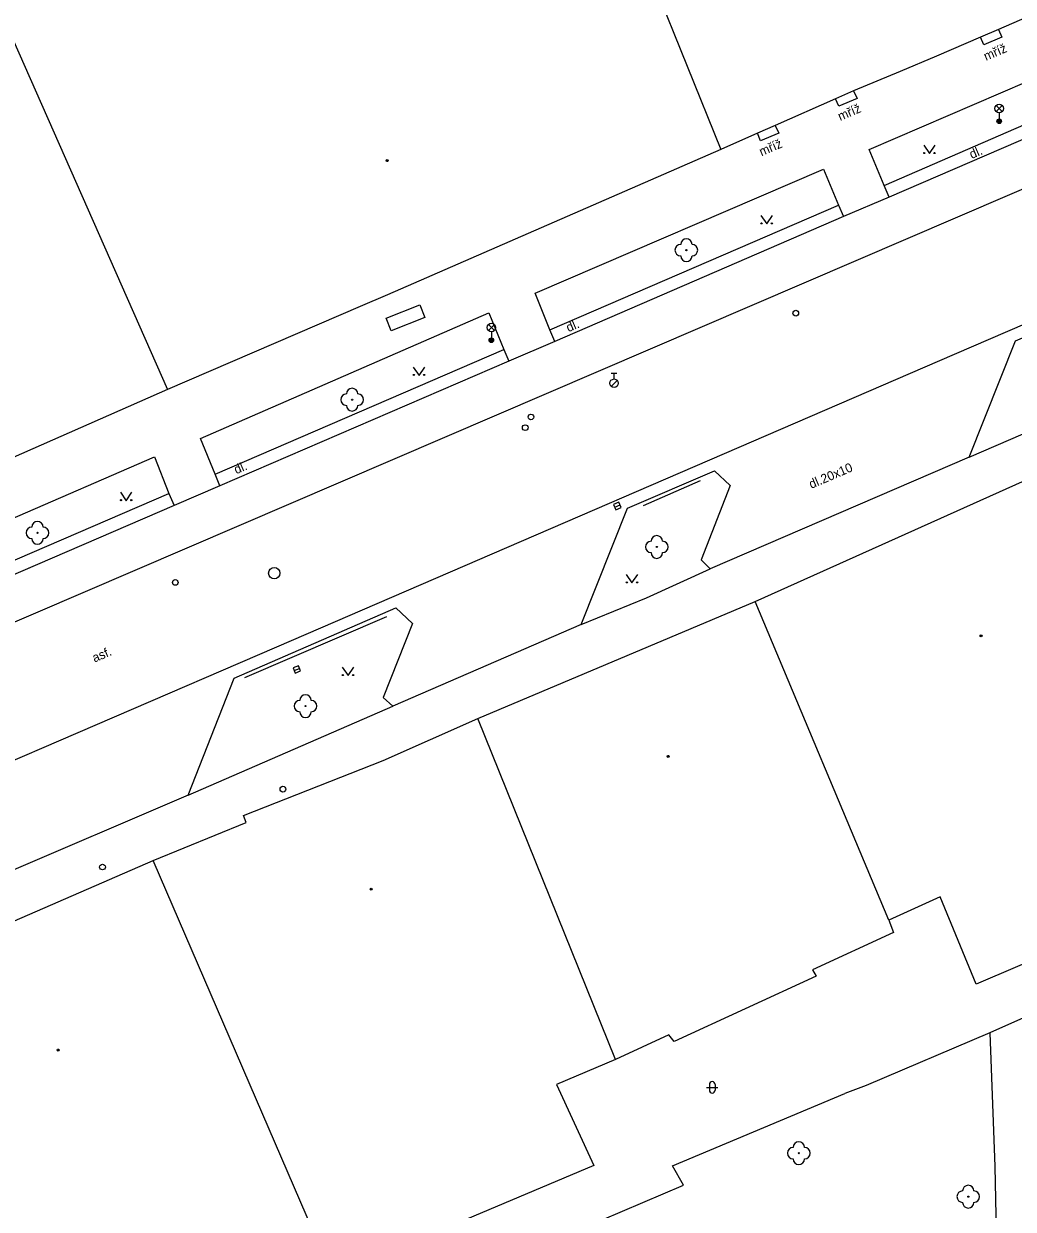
# Model space of a CAD drawing. Extents: x -599770 to -598493, y -1162076 to -1159209.
# Drawn here: x -599478.9 to -599435.5, y -1161229.9 to -1161177.8 of the extents above; entities that cross this region are included whole.
import ezdxf

# ---------------------------------------------------------------- set-up
doc = ezdxf.new("R2010")
doc.units = 0
doc.layers.add('Podklad', color=7, linetype='Continuous')

msp = doc.modelspace()

# ---------------------------------------------------------------- linework, layer by layer
at = {"layer": 'Podklad'}
for p, q in [((-599436.203, -1161181.68), (-599435.938, -1161181.415)), ((-599436.203, -1161181.415), (-599435.938, -1161181.68)), ((-599436.07, -1161181.735), (-599436.07, -1161182.11)), ((-599458.523, -1161191.3), (-599458.258, -1161191.035)), ((-599458.523, -1161191.035), (-599458.258, -1161191.3)), ((-599458.39, -1161191.355), (-599458.39, -1161191.73)), ((-599453.125, -1161193.183), (-599452.875, -1161193.183)), ((-599453, -1161193.433), (-599453, -1161193.183)), ((-599453.129, -1161193.756), (-599452.864, -1161193.491)), ((-599452.964, -1161199.06), (-599452.736, -1161198.96)), ((-599467.055, -1161206.238), (-599466.825, -1161206.142)), ((-599448.933, -1161224.548), (-599448.433, -1161224.548)), ((-599448.808, -1161224.423), (-599448.808, -1161224.673)), ((-599448.558, -1161224.423), (-599448.558, -1161224.673))]:
    msp.add_line(p, q, dxfattribs=at)
for points in [[(-599452.75, -1161172.35), (-599448.3, -1161183.35)], [(-599433.37, -1161176.9), (-599436.1, -1161178.08)], [(-599517.213, -1161220.408), (-599480.808, -1161204.724), (-599417.53, -1161177.569)], [(-599479.66, -1161177.97), (-599472.63, -1161193.89)], [(-599441.12, -1161184.93), (-599441.78, -1161183.35), (-599429.05, -1161177.88), (-599428.41, -1161179.41)], [(-599436.1, -1161178.08), (-599436.9, -1161178.42)], [(-599436.1, -1161178.08), (-599435.95, -1161178.42), (-599436.75, -1161178.76), (-599436.9, -1161178.42)], [(-599436.9, -1161178.42), (-599438.83, -1161179.25)], [(-599438.83, -1161179.25), (-599440.43, -1161179.93)], [(-599441.12, -1161184.93), (-599428.41, -1161179.41)], [(-599440.43, -1161179.93), (-599442.47, -1161180.78)], [(-599428.17, -1161179.95), (-599440.91, -1161185.44)], [(-599442.47, -1161180.78), (-599443.27, -1161181.12)], [(-599442.47, -1161180.78), (-599442.32, -1161181.11), (-599443.12, -1161181.45), (-599443.27, -1161181.12)], [(-599443.27, -1161181.12), (-599445.91, -1161182.29)], [(-599445.91, -1161182.29), (-599446.7, -1161182.64)], [(-599445.91, -1161182.29), (-599445.76, -1161182.63), (-599446.56, -1161182.97), (-599446.7, -1161182.64)], [(-599416, -1161182.85), (-599438.05, -1161192.36), (-599467.84, -1161205.21), (-599482.11, -1161211.36), (-599501.88, -1161219.89), (-599514.52, -1161225.34), (-599535.02, -1161234.19), (-599553.39, -1161242.12)], [(-599446.7, -1161182.64), (-599448.3, -1161183.35)], [(-599448.3, -1161183.35), (-599462.95, -1161189.74)], [(-599439.39, -1161183.155), (-599439.14, -1161183.53), (-599438.89, -1161183.155)], [(-599455.82, -1161191.27), (-599456.47, -1161189.66), (-599443.8, -1161184.22), (-599443.13, -1161185.79)], [(-599440.91, -1161185.44), (-599441.12, -1161184.93)], [(-599440.91, -1161185.44), (-599442.91, -1161186.3)], [(-599455.82, -1161191.27), (-599443.13, -1161185.79)], [(-599443.13, -1161185.79), (-599442.91, -1161186.3)], [(-599442.91, -1161186.3), (-599455.6, -1161191.78)], [(-599446.54, -1161186.245), (-599446.29, -1161186.62), (-599446.04, -1161186.245)], [(-599462.95, -1161189.74), (-599464.16, -1161190.25)], [(-599437.39, -1161196.87), (-599435.35, -1161191.75), (-599430.57, -1161189.69), (-599429.87, -1161190.33), (-599431.23, -1161193.61), (-599430.82, -1161194.02)], [(-599464.16, -1161190.25), (-599472.63, -1161193.89)], [(-599463.02, -1161190.76), (-599461.53, -1161190.17), (-599461.31, -1161190.73)], [(-599470.53, -1161197.61), (-599471.18, -1161196.04), (-599458.5, -1161190.52), (-599457.84, -1161192.14)], [(-599461.31, -1161190.73), (-599462.79, -1161191.31), (-599463.02, -1161190.76)], [(-599455.6, -1161191.78), (-599455.82, -1161191.27)], [(-599455.6, -1161191.78), (-599457.62, -1161192.65)], [(-599470.53, -1161197.61), (-599457.84, -1161192.14)], [(-599457.84, -1161192.14), (-599457.62, -1161192.65)], [(-599457.62, -1161192.65), (-599470.33, -1161198.13)], [(-599461.82, -1161192.905), (-599461.57, -1161193.28), (-599461.32, -1161192.905)], [(-599472.63, -1161193.89), (-599485.84, -1161199.7)], [(-599437.39, -1161196.87), (-599430.82, -1161194.02)], [(-599446.8, -1161203.21), (-599431.33, -1161196.26)], [(-599485.24, -1161203.92), (-599485.9, -1161202.36), (-599473.19, -1161196.85), (-599472.56, -1161198.46)], [(-599437.39, -1161196.87), (-599448.78, -1161201.77)], [(-599454.44, -1161204.22), (-599452.4, -1161199.11), (-599448.58, -1161197.46), (-599447.9, -1161198.11), (-599449.17, -1161201.38), (-599448.78, -1161201.77)], [(-599470.33, -1161198.13), (-599470.53, -1161197.61)], [(-599451.7, -1161198.99), (-599449.2, -1161197.89)], [(-599485.24, -1161203.92), (-599472.56, -1161198.46)], [(-599474.69, -1161198.405), (-599474.44, -1161198.78), (-599474.19, -1161198.405)], [(-599472.56, -1161198.46), (-599472.33, -1161198.99)], [(-599470.33, -1161198.13), (-599472.33, -1161198.99)], [(-599472.33, -1161198.99), (-599485.1, -1161204.5)], [(-599454.44, -1161204.22), (-599451.57, -1161203.05), (-599448.78, -1161201.77)], [(-599452.46, -1161202.015), (-599452.21, -1161202.39), (-599451.96, -1161202.015)], [(-599458.99, -1161208.35), (-599446.8, -1161203.21)], [(-599440.92, -1161217.2), (-599446.8, -1161203.21)], [(-599471.72, -1161211.71), (-599469.7, -1161206.57), (-599462.59, -1161203.49), (-599461.86, -1161204.17), (-599463.15, -1161207.42), (-599462.72, -1161207.81)], [(-599469.23, -1161206.54), (-599462.98, -1161203.87)], [(-599454.44, -1161204.22), (-599462.72, -1161207.81)], [(-599464.94, -1161206.085), (-599464.69, -1161206.46), (-599464.44, -1161206.085)], [(-599471.72, -1161211.71), (-599462.72, -1161207.81)], [(-599463.15, -1161210.19), (-599458.99, -1161208.35)], [(-599452.94, -1161223.32), (-599458.99, -1161208.35)], [(-599469.28, -1161212.6), (-599463.15, -1161210.19)], [(-599471.72, -1161211.71), (-599480, -1161215.26)], [(-599469.17, -1161212.91), (-599469.28, -1161212.6)], [(-599473.25, -1161214.59), (-599469.17, -1161212.91)], [(-599487.38, -1161220.72), (-599473.25, -1161214.59)], [(-599465.37, -1161232.83), (-599473.25, -1161214.59)], [(-599438.66, -1161216.18), (-599440.92, -1161217.2)], [(-599437.08, -1161220.02), (-599438.66, -1161216.18)], [(-599440.92, -1161217.2), (-599440.72, -1161217.75)], [(-599440.72, -1161217.75), (-599444.28, -1161219.38)], [(-599431.63, -1161217.69), (-599437.08, -1161220.02)], [(-599444.28, -1161219.38), (-599444.12, -1161219.67)], [(-599429.8, -1161219.18), (-599436.49, -1161222.15), (-599441.92, -1161224.46)], [(-599444.12, -1161219.67), (-599450.35, -1161222.53)], [(-599450.59, -1161222.24), (-599452.94, -1161223.32)], [(-599450.35, -1161222.53), (-599450.59, -1161222.24)], [(-599436.49, -1161222.15), (-599436.26, -1161228.02), (-599436.21, -1161230.9)], [(-599452.94, -1161223.32), (-599455.53, -1161224.43)], [(-599455.53, -1161224.43), (-599453.89, -1161227.98)], [(-599441.92, -1161224.46), (-599442.85, -1161224.82)], [(-599450.43, -1161227.99), (-599442.85, -1161224.82)], [(-599453.89, -1161227.98), (-599465.37, -1161232.83)], [(-599449.94, -1161228.84), (-599450.43, -1161227.99)], [(-599464.24, -1161234.93), (-599449.94, -1161228.84)]]:
    msp.add_lwpolyline(points, dxfattribs=at)
for points in [[(-599452.914, -1161199.175), (-599452.685, -1161199.074), (-599452.786, -1161198.845), (-599453.015, -1161198.946)], [(-599467.008, -1161206.353), (-599466.777, -1161206.258), (-599466.872, -1161206.027), (-599467.103, -1161206.122)]]:
    msp.add_lwpolyline(points, close=True, dxfattribs=at)
for centre, radius in [((-599436.07, -1161181.547), 0.188), ((-599436.07, -1161182.11), 0.1), ((-599436.07, -1161182.11), 0.0723), ((-599436.07, -1161182.11), 0.0438), ((-599439.365, -1161183.505), 0.025), ((-599438.915, -1161183.505), 0.025), ((-599462.97, -1161183.84), 0.045), ((-599462.97, -1161183.84), 0.0199), ((-599446.515, -1161186.595), 0.025), ((-599446.065, -1161186.595), 0.025), ((-599449.82, -1161187.77), 0.025), ((-599445.01, -1161190.54), 0.125), ((-599458.39, -1161191.168), 0.188), ((-599458.39, -1161191.73), 0.1), ((-599458.39, -1161191.73), 0.0723), ((-599458.39, -1161191.73), 0.0438), ((-599461.795, -1161193.255), 0.025), ((-599461.345, -1161193.255), 0.025), ((-599453, -1161193.62), 0.188), ((-599464.51, -1161194.34), 0.025), ((-599456.9, -1161195.57), 0.125), ((-599456.65, -1161195.1), 0.125), ((-599474.665, -1161198.755), 0.025), ((-599474.215, -1161198.755), 0.025), ((-599478.34, -1161200.19), 0.025), ((-599451.12, -1161200.81), 0.025), ((-599467.93, -1161201.96), 0.25), ((-599472.28, -1161202.37), 0.125), ((-599452.435, -1161202.365), 0.025), ((-599451.985, -1161202.365), 0.025), ((-599436.87, -1161204.71), 0.045), ((-599436.87, -1161204.71), 0.0199), ((-599464.915, -1161206.435), 0.025), ((-599464.465, -1161206.435), 0.025), ((-599466.56, -1161207.8), 0.025), ((-599450.62, -1161210.01), 0.045), ((-599450.62, -1161210.01), 0.0199), ((-599467.55, -1161211.45), 0.125), ((-599475.48, -1161214.87), 0.125), ((-599463.67, -1161215.84), 0.045), ((-599463.67, -1161215.84), 0.0199), ((-599477.43, -1161222.91), 0.045), ((-599477.43, -1161222.91), 0.0199), ((-599444.88, -1161227.44), 0.025), ((-599437.43, -1161229.35), 0.025)]:
    msp.add_circle(centre, radius, dxfattribs=at)
for centre, radius, start, end in [((-599450.07, -1161187.77), 0.25, 90, 270), ((-599449.82, -1161187.52), 0.25, 0, 180), ((-599449.57, -1161187.77), 0.25, 270, 90), ((-599449.82, -1161188.02), 0.25, 180, 0), ((-599464.51, -1161194.09), 0.25, 0, 180), ((-599464.76, -1161194.34), 0.25, 90, 270), ((-599464.26, -1161194.34), 0.25, 270, 90), ((-599464.51, -1161194.59), 0.25, 180, 0), ((-599478.59, -1161200.19), 0.25, 90, 270), ((-599478.34, -1161199.94), 0.25, 0, 180), ((-599478.09, -1161200.19), 0.25, 270, 90), ((-599478.34, -1161200.44), 0.25, 180, 0), ((-599451.37, -1161200.81), 0.25, 90, 270), ((-599451.12, -1161200.56), 0.25, 0, 180), ((-599450.87, -1161200.81), 0.25, 270, 90), ((-599451.12, -1161201.06), 0.25, 180, 0), ((-599466.56, -1161207.55), 0.25, 0, 180), ((-599466.81, -1161207.8), 0.25, 90, 270), ((-599466.31, -1161207.8), 0.25, 270, 90), ((-599466.56, -1161208.05), 0.25, 180, 0), ((-599448.683, -1161224.423), 0.125, 0, 180), ((-599448.683, -1161224.673), 0.125, 180, 0), ((-599445.13, -1161227.44), 0.25, 90, 270), ((-599444.88, -1161227.19), 0.25, 0, 180), ((-599444.63, -1161227.44), 0.25, 270, 90), ((-599444.88, -1161227.69), 0.25, 180, 0), ((-599437.68, -1161229.35), 0.25, 90, 270), ((-599437.43, -1161229.1), 0.25, 0, 180), ((-599437.18, -1161229.35), 0.25, 270, 90), ((-599437.43, -1161229.6), 0.25, 180, 0)]:
    msp.add_arc(centre, radius, start, end, dxfattribs=at)

# ---------------------------------------------------------------- texts
for s, rotation, p in [('mříž', 23.1401, (-599436.65, -1161179.46)), ('mříž', 23.1401, (-599443.06, -1161182.1)), ('mříž', 23.1401, (-599446.52, -1161183.65)), ('dl.', 23.25, (-599437.28, -1161183.77)), ('dl.', 23.25, (-599455, -1161191.38)), ('dl.', 23.25, (-599469.6, -1161197.62)), ('dl.20x10', 23.1401, (-599444.33, -1161198.26)), ('asf.', 23, (-599475.83, -1161205.89))]:
    msp.add_text(s, height=0.4, rotation=rotation, dxfattribs=at).set_placement(p)

doc.saveas('drawing.dxf')
